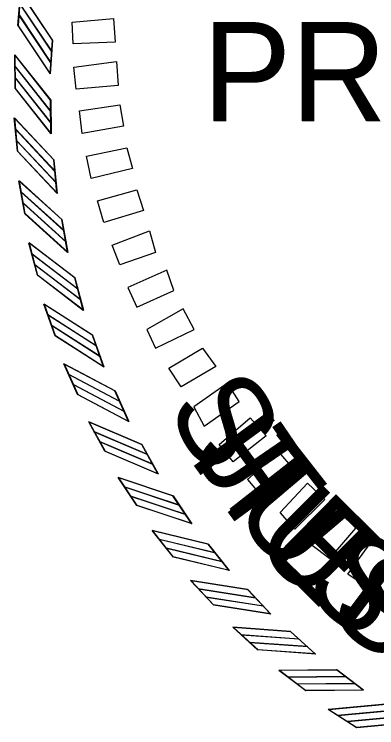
# Model space of a CAD drawing. Extents: x 16 to 1228740, y 11 to 152440.
# Drawn here: x 17.6792 to 17.7202, y 10.8292 to 10.9098 of the extents above; entities that cross this region are included whole.
import ezdxf

# ---------------------------------------------------------------- set-up
doc = ezdxf.new("R2010")
doc.units = 0
for name, color, linetype in [('STAMP_FRED', 7, 'Continuous'), ('STAMP_HUSSAM', 7, 'Continuous'), ('STAMP_JUSTIN', 7, 'Continuous'), ('STAMP_PRELIM', 7, 'Continuous')]:
    doc.layers.add(name, color=color, linetype=linetype)

msp = doc.modelspace()

# ---------------------------------------------------------------- linework, layer by layer
at = {"layer": 'STAMP_FRED'}
for p, q in [((17.6797, 10.908524), (17.679977, 10.912284)), ((17.683323, 10.903099), (17.683601, 10.906868)), ((17.67937, 10.901425), (17.679335, 10.905195)), ((17.683429, 10.896318), (17.683394, 10.900096)), ((17.679627, 10.894324), (17.679282, 10.898078)), ((17.684094, 10.889569), (17.683748, 10.893331)), ((17.680471, 10.887267), (17.679816, 10.89098)), ((17.685315, 10.882897), (17.684658, 10.886619)), ((17.681893, 10.880305), (17.680934, 10.883951)), ((17.687082, 10.87635), (17.686121, 10.880004)), ((17.683886, 10.873483), (17.682629, 10.877038)), ((17.689384, 10.86997), (17.688124, 10.873533)), ((17.686436, 10.86685), (17.68489, 10.870288)), ((17.692204, 10.863803), (17.690655, 10.867249)), ((17.689524, 10.86045), (17.6877, 10.863749)), ((17.695525, 10.857889), (17.693696, 10.861196)), ((17.693131, 10.854326), (17.69104, 10.857463)), ((17.699322, 10.85227), (17.697227, 10.855415)), ((17.697231, 10.848522), (17.694888, 10.851475)), ((17.703571, 10.846984), (17.701223, 10.849945)), ((17.701796, 10.843075), (17.699217, 10.845825)), ((17.708241, 10.842067), (17.705657, 10.844823)), ((17.706795, 10.838025), (17.703998, 10.840552)), ((17.713302, 10.837552), (17.710498, 10.840085)), ((17.712195, 10.833404), (17.709198, 10.835692)), ((17.718718, 10.83347), (17.715715, 10.835764)), ((17.717957, 10.829245), (17.714782, 10.831278))]:
    msp.add_line(p, q, dxfattribs=at)
for points in [[(17.683598, 10.906863), (17.679974, 10.912288)], [(17.683494, 10.905612), (17.679871, 10.911036)], [(17.683427, 10.904304), (17.679803, 10.909728)], [(17.683326, 10.903094), (17.679703, 10.908519)], [(17.683392, 10.900092), (17.679333, 10.905199)], [(17.683392, 10.898836), (17.679333, 10.903943)], [(17.683433, 10.897527), (17.679374, 10.902633)], [(17.683433, 10.896313), (17.679374, 10.90142)], [(17.683745, 10.893327), (17.679279, 10.898081)], [(17.683849, 10.892075), (17.679382, 10.896829)], [(17.683998, 10.890774), (17.679531, 10.895528)], [(17.684098, 10.889565), (17.679632, 10.894319)], [(17.684657, 10.886614), (17.679813, 10.890983)], [(17.684863, 10.885375), (17.680019, 10.889744)], [(17.685119, 10.884091), (17.680275, 10.888459)], [(17.685319, 10.882894), (17.680475, 10.887263)], [(17.686119, 10.879999), (17.680931, 10.883953)], [(17.686427, 10.878782), (17.681239, 10.882736)], [(17.686789, 10.877523), (17.6816, 10.881477)], [(17.687086, 10.876346), (17.681898, 10.8803)], [(17.688123, 10.873528), (17.682626, 10.87704)], [(17.688531, 10.87234), (17.683034, 10.875852)], [(17.688995, 10.871115), (17.683497, 10.874627)], [(17.689389, 10.869967), (17.683891, 10.873479)], [(17.690654, 10.867244), (17.684886, 10.87029)], [(17.691159, 10.866094), (17.68539, 10.86914)], [(17.691722, 10.864912), (17.685954, 10.867958)], [(17.69221, 10.8638), (17.686441, 10.866846)], [(17.693696, 10.861191), (17.687696, 10.86375)], [(17.694293, 10.860086), (17.688293, 10.862646)], [(17.694953, 10.858954), (17.688953, 10.861514)], [(17.69553, 10.857887), (17.68953, 10.860447)], [(17.697227, 10.855409), (17.691036, 10.857465)], [(17.697914, 10.854358), (17.691723, 10.856413)], [(17.698664, 10.853284), (17.692473, 10.85534)], [(17.699328, 10.852269), (17.693137, 10.854324)], [(17.701223, 10.849939), (17.694884, 10.851476)], [(17.701995, 10.848948), (17.695655, 10.850485)], [(17.702831, 10.84794), (17.696492, 10.849477)], [(17.703576, 10.846983), (17.697237, 10.84852)], [(17.705658, 10.844818), (17.699213, 10.845826)], [(17.706508, 10.843894), (17.700063, 10.844902)], [(17.707425, 10.842959), (17.70098, 10.843967)], [(17.708247, 10.842066), (17.701802, 10.843074)], [(17.7105, 10.84008), (17.703994, 10.840553)], [(17.711424, 10.83923), (17.704918, 10.839702)], [(17.712415, 10.838373), (17.705909, 10.838846)], [(17.713308, 10.837551), (17.706802, 10.838024)], [(17.715717, 10.835759), (17.709194, 10.835692)], [(17.716708, 10.834987), (17.710185, 10.834921)], [(17.717766, 10.834216), (17.711243, 10.834149)], [(17.718724, 10.83347), (17.712201, 10.833404)], [(17.721273, 10.831883), (17.714778, 10.831278)], [(17.722324, 10.831196), (17.715829, 10.830591)], [(17.723443, 10.830514), (17.716948, 10.829909)], [(17.724459, 10.82985), (17.717964, 10.829245)]]:
    msp.add_lwpolyline(points, dxfattribs=at)
at = {"layer": 'STAMP_HUSSAM'}
for p, q in [((17.679644, 10.908555), (17.679921, 10.912315)), ((17.683267, 10.90313), (17.683545, 10.906898)), ((17.679314, 10.901456), (17.67928, 10.905226)), ((17.683373, 10.896349), (17.683338, 10.900127)), ((17.679572, 10.894354), (17.679226, 10.898108)), ((17.684039, 10.8896), (17.683692, 10.893362)), ((17.680415, 10.887298), (17.67976, 10.891011)), ((17.685259, 10.882928), (17.684603, 10.88665)), ((17.681838, 10.880335), (17.680879, 10.883981)), ((17.687026, 10.876381), (17.686065, 10.880035)), ((17.683831, 10.873514), (17.682574, 10.877068)), ((17.689328, 10.870001), (17.688068, 10.873564)), ((17.68638, 10.866881), (17.684834, 10.870319)), ((17.692149, 10.863834), (17.690599, 10.86728)), ((17.689469, 10.86048), (17.687644, 10.863779)), ((17.695469, 10.85792), (17.69364, 10.861227)), ((17.693075, 10.854357), (17.690984, 10.857494)), ((17.699267, 10.852301), (17.697171, 10.855446)), ((17.697175, 10.848552), (17.694832, 10.851506)), ((17.703515, 10.847015), (17.701167, 10.849975)), ((17.70174, 10.843106), (17.699161, 10.845856)), ((17.708186, 10.842098), (17.705601, 10.844854)), ((17.706739, 10.838056), (17.703942, 10.840583)), ((17.713246, 10.837583), (17.710443, 10.840116)), ((17.712139, 10.833435), (17.709143, 10.835723)), ((17.718662, 10.833501), (17.715659, 10.835794)), ((17.717901, 10.829276), (17.714726, 10.831309))]:
    msp.add_line(p, q, dxfattribs=at)
for points in [[(17.683542, 10.906894), (17.679918, 10.912319)], [(17.683438, 10.905643), (17.679815, 10.911067)], [(17.683371, 10.904334), (17.679748, 10.909759)], [(17.683271, 10.903125), (17.679647, 10.908549)], [(17.683336, 10.900123), (17.679277, 10.905229)], [(17.683336, 10.898867), (17.679277, 10.903974)], [(17.683377, 10.897558), (17.679318, 10.902664)], [(17.683377, 10.896344), (17.679318, 10.901451)], [(17.68369, 10.893358), (17.679223, 10.898112)], [(17.683793, 10.892106), (17.679327, 10.89686)], [(17.683942, 10.890805), (17.679476, 10.895559)], [(17.684042, 10.889595), (17.679576, 10.894349)], [(17.684601, 10.886645), (17.679757, 10.891014)], [(17.684808, 10.885406), (17.679964, 10.889775)], [(17.685063, 10.884121), (17.680219, 10.88849)], [(17.685263, 10.882924), (17.680419, 10.887293)], [(17.686063, 10.88003), (17.680875, 10.883984)], [(17.686372, 10.878813), (17.681183, 10.882767)], [(17.686733, 10.877553), (17.681545, 10.881507)], [(17.687031, 10.876377), (17.681842, 10.880331)], [(17.688067, 10.873559), (17.68257, 10.877071)], [(17.688475, 10.872371), (17.682978, 10.875883)], [(17.688939, 10.871146), (17.683442, 10.874658)], [(17.689333, 10.869998), (17.683836, 10.87351)], [(17.690598, 10.867275), (17.68483, 10.870321)], [(17.691103, 10.866125), (17.685335, 10.869171)], [(17.691666, 10.864942), (17.685898, 10.867988)], [(17.692154, 10.863831), (17.686385, 10.866877)], [(17.69364, 10.861222), (17.68764, 10.863781)], [(17.694238, 10.860117), (17.688238, 10.862677)], [(17.694897, 10.858985), (17.688897, 10.861545)], [(17.695474, 10.857918), (17.689474, 10.860477)], [(17.697171, 10.85544), (17.69098, 10.857495)], [(17.697858, 10.854389), (17.691667, 10.856444)], [(17.698608, 10.853315), (17.692417, 10.85537)], [(17.699272, 10.852299), (17.693081, 10.854355)], [(17.701167, 10.84997), (17.694828, 10.851507)], [(17.701939, 10.848979), (17.695599, 10.850516)], [(17.702775, 10.847971), (17.696436, 10.849508)], [(17.703521, 10.847014), (17.697181, 10.84855)], [(17.705602, 10.844849), (17.699157, 10.845857)], [(17.706453, 10.843925), (17.700008, 10.844933)], [(17.707369, 10.842989), (17.700925, 10.843997)], [(17.708191, 10.842097), (17.701746, 10.843105)], [(17.710444, 10.840111), (17.703938, 10.840584)], [(17.711368, 10.839261), (17.704862, 10.839733)], [(17.712359, 10.838404), (17.705853, 10.838876)], [(17.713252, 10.837582), (17.706746, 10.838055)], [(17.715661, 10.83579), (17.709138, 10.835723)], [(17.716652, 10.835018), (17.710129, 10.834952)], [(17.717711, 10.834246), (17.711188, 10.83418)], [(17.718668, 10.833501), (17.712145, 10.833435)], [(17.721217, 10.831914), (17.714722, 10.831309)], [(17.722269, 10.831227), (17.715773, 10.830622)], [(17.723387, 10.830545), (17.716892, 10.82994)], [(17.724403, 10.829881), (17.717908, 10.829276)]]:
    msp.add_lwpolyline(points, dxfattribs=at)
at = {"layer": 'STAMP_JUSTIN'}
for p, q in [((17.679702, 10.908525), (17.679979, 10.912285)), ((17.683325, 10.9031), (17.683602, 10.906868)), ((17.679372, 10.901426), (17.679337, 10.905196)), ((17.683431, 10.896319), (17.683396, 10.900097)), ((17.679629, 10.894325), (17.679283, 10.898079)), ((17.684096, 10.88957), (17.683749, 10.893333)), ((17.680472, 10.887269), (17.679818, 10.890981)), ((17.685316, 10.882899), (17.68466, 10.88662)), ((17.681895, 10.880306), (17.680936, 10.883952)), ((17.687084, 10.876351), (17.686122, 10.880006)), ((17.683888, 10.873485), (17.682631, 10.877039)), ((17.689385, 10.869972), (17.688126, 10.873535)), ((17.686437, 10.866852), (17.684891, 10.87029)), ((17.692206, 10.863805), (17.690656, 10.867251)), ((17.689526, 10.860452), (17.687701, 10.86375)), ((17.695526, 10.857891), (17.693697, 10.861198)), ((17.693132, 10.854328), (17.691042, 10.857465)), ((17.699324, 10.852273), (17.697228, 10.855417)), ((17.697232, 10.848524), (17.694889, 10.851477)), ((17.703572, 10.846986), (17.701224, 10.849947)), ((17.701797, 10.843078), (17.699219, 10.845828)), ((17.708243, 10.842069), (17.705658, 10.844825)), ((17.706796, 10.838027), (17.704, 10.840555)), ((17.713303, 10.837554), (17.7105, 10.840088)), ((17.712196, 10.833407), (17.7092, 10.835695)), ((17.718719, 10.833473), (17.715716, 10.835766)), ((17.717958, 10.829248), (17.714783, 10.831281))]:
    msp.add_line(p, q, dxfattribs=at)
for points in [[(17.683599, 10.906864), (17.679976, 10.912288)], [(17.683496, 10.905613), (17.679872, 10.911037)], [(17.683428, 10.904304), (17.679805, 10.909729)], [(17.683328, 10.903095), (17.679705, 10.908519)], [(17.683393, 10.900093), (17.679335, 10.9052)], [(17.683393, 10.898837), (17.679335, 10.903944)], [(17.683434, 10.897528), (17.679376, 10.902634)], [(17.683434, 10.896314), (17.679376, 10.901421)], [(17.683747, 10.893328), (17.67928, 10.898082)], [(17.683851, 10.892076), (17.679384, 10.89683)], [(17.684, 10.890775), (17.679533, 10.895529)], [(17.6841, 10.889566), (17.679633, 10.89432)], [(17.684658, 10.886615), (17.679814, 10.890984)], [(17.684865, 10.885376), (17.680021, 10.889745)], [(17.685121, 10.884092), (17.680277, 10.888461)], [(17.685321, 10.882895), (17.680477, 10.887264)], [(17.686121, 10.880001), (17.680933, 10.883955)], [(17.686429, 10.878783), (17.681241, 10.882737)], [(17.68679, 10.877524), (17.681602, 10.881478)], [(17.687088, 10.876348), (17.6819, 10.880302)], [(17.688125, 10.87353), (17.682628, 10.877041)], [(17.688532, 10.872342), (17.683035, 10.875854)], [(17.688996, 10.871117), (17.683499, 10.874629)], [(17.68939, 10.869969), (17.683893, 10.873481)], [(17.690656, 10.867246), (17.684888, 10.870292)], [(17.69116, 10.866096), (17.685392, 10.869142)], [(17.691724, 10.864913), (17.685956, 10.867959)], [(17.692211, 10.863802), (17.686443, 10.866848)], [(17.693697, 10.861193), (17.687697, 10.863752)], [(17.694295, 10.860088), (17.688295, 10.862648)], [(17.694954, 10.858956), (17.688954, 10.861516)], [(17.695532, 10.857889), (17.689532, 10.860449)], [(17.697228, 10.855412), (17.691037, 10.857467)], [(17.697915, 10.85436), (17.691724, 10.856415)], [(17.698666, 10.853287), (17.692475, 10.855342)], [(17.699329, 10.852271), (17.693138, 10.854326)], [(17.701225, 10.849942), (17.694885, 10.851478)], [(17.701996, 10.848951), (17.695656, 10.850487)], [(17.702832, 10.847943), (17.696493, 10.849479)], [(17.703578, 10.846985), (17.697238, 10.848522)], [(17.705659, 10.84482), (17.699214, 10.845828)], [(17.70651, 10.843896), (17.700065, 10.844904)], [(17.707426, 10.842961), (17.700982, 10.843969)], [(17.708248, 10.842068), (17.701804, 10.843076)], [(17.710501, 10.840083), (17.703995, 10.840555)], [(17.711425, 10.839232), (17.704919, 10.839705)], [(17.712416, 10.838376), (17.70591, 10.838848)], [(17.713309, 10.837554), (17.706803, 10.838026)], [(17.715718, 10.835761), (17.709195, 10.835695)], [(17.716709, 10.83499), (17.710186, 10.834923)], [(17.717767, 10.834218), (17.711245, 10.834152)], [(17.718725, 10.833473), (17.712202, 10.833406)], [(17.721274, 10.831885), (17.714779, 10.83128)], [(17.722325, 10.831198), (17.71583, 10.830593)], [(17.723444, 10.830517), (17.716949, 10.829912)], [(17.724459, 10.829853), (17.717964, 10.829248)]]:
    msp.add_lwpolyline(points, dxfattribs=at)
at = {"layer": 'STAMP_PRELIM'}
for p, q in [((17.685777, 10.908908), (17.69046, 10.90935)), ((17.69046, 10.90935), (17.690652, 10.906658)), ((17.685902, 10.906475), (17.685777, 10.908908)), ((17.690652, 10.906658), (17.685902, 10.906475)), ((17.68596, 10.90385), (17.690777, 10.904475)), ((17.690777, 10.904475), (17.69096, 10.901783)), ((17.68621, 10.90135), (17.68596, 10.90385)), ((17.69096, 10.901783), (17.68621, 10.90135)), ((17.686585, 10.898908), (17.691152, 10.8996)), ((17.691152, 10.8996), (17.691585, 10.897158)), ((17.686902, 10.89635), (17.686585, 10.898908)), ((17.691585, 10.897158), (17.686902, 10.89635)), ((17.687402, 10.893783), (17.69196, 10.894725)), ((17.69196, 10.894725), (17.692585, 10.892408)), ((17.687902, 10.891283), (17.687402, 10.893783)), ((17.692585, 10.892408), (17.687902, 10.891283)), ((17.688652, 10.888725), (17.693085, 10.889975)), ((17.693085, 10.889975), (17.693835, 10.887658)), ((17.689335, 10.886283), (17.688652, 10.888725)), ((17.693835, 10.887658), (17.689335, 10.886283)), ((17.690277, 10.883725), (17.694527, 10.88535)), ((17.694527, 10.88535), (17.69521, 10.882908)), ((17.691152, 10.881533), (17.690277, 10.883725)), ((17.69521, 10.882908), (17.691152, 10.881533)), ((17.69646, 10.880908), (17.692085, 10.878975)), ((17.697277, 10.8786), (17.69646, 10.880908)), ((17.692085, 10.878975), (17.693085, 10.876725)), ((17.693085, 10.876725), (17.697277, 10.8786)), ((17.698335, 10.876533), (17.69421, 10.874225)), ((17.699585, 10.874225), (17.698335, 10.876533)), ((17.69421, 10.874225), (17.69521, 10.8721)), ((17.69521, 10.8721), (17.699585, 10.874225)), ((17.69671, 10.86985), (17.700527, 10.8721)), ((17.700527, 10.8721), (17.702027, 10.870033)), ((17.698085, 10.867725), (17.69671, 10.86985)), ((17.702027, 10.870033), (17.698085, 10.867725)), ((17.703335, 10.868158), (17.699527, 10.865475)), ((17.704652, 10.8661), (17.703335, 10.868158)), ((17.70071, 10.863283), (17.704652, 10.8661)), ((17.699527, 10.865475), (17.70071, 10.863283)), ((17.702402, 10.861225), (17.705902, 10.864225)), ((17.705902, 10.864225), (17.70771, 10.862225)), ((17.70771, 10.862225), (17.70396, 10.859283)), ((17.70396, 10.859283), (17.702402, 10.861225)), ((17.709152, 10.860408), (17.705585, 10.857283)), ((17.710777, 10.858533), (17.709152, 10.860408)), ((17.70721, 10.85535), (17.710777, 10.858533)), ((17.705585, 10.857283), (17.70721, 10.85535)), ((17.709277, 10.853533), (17.712402, 10.85685)), ((17.712402, 10.85685), (17.714335, 10.855033)), ((17.714335, 10.855033), (17.71096, 10.851658)), ((17.71096, 10.851658), (17.709277, 10.853533)), ((17.716027, 10.853533), (17.712777, 10.849975)), ((17.717835, 10.851783), (17.716027, 10.853533)), ((17.714902, 10.84835), (17.717835, 10.851783)), ((17.71696, 10.8466), (17.719777, 10.850475)), ((17.719777, 10.850475), (17.72171, 10.848908)), ((17.712777, 10.849975), (17.714902, 10.84835)), ((17.72171, 10.848908), (17.718902, 10.845283)), ((17.718902, 10.845283), (17.71696, 10.8466))]:
    msp.add_line(p, q, dxfattribs=at)

# ---------------------------------------------------------------- texts
at = {"layer": 'STAMP_FRED'}
msp.add_text('PROFESSIONAL', height=0.01119382, dxfattribs=at).set_placement((17.700561, 10.897711))
for s, rotation, p in [('S', 300.79847, (17.696258, 10.865347)), ('T', 308.09448, (17.701345, 10.856814)), ('E', 315.39049, (17.707475, 10.848997)), ('P', 323.0513, (17.714924, 10.841696))]:
    msp.add_text(s, height=0.010417, rotation=rotation, dxfattribs=at).set_placement(p)
at = {"layer": 'STAMP_HUSSAM'}
msp.add_text('PROFESSIONAL', height=0.01119382, dxfattribs=at).set_placement((17.700506, 10.897742))
for s, rotation, p in [('H', 306.22623, (17.69885, 10.859742)), ('U', 314.9716, (17.7059, 10.850121)), ('S', 323.71697, (17.714331, 10.841684))]:
    msp.add_text(s, height=0.010417, rotation=rotation, dxfattribs=at).set_placement(p)
at = {"layer": 'STAMP_JUSTIN'}
msp.add_text('PROFESSIONAL', height=0.01119355, dxfattribs=at).set_placement((17.700563, 10.897712))
for s, rotation, p in [('J', 304.36793, (17.699173, 10.860274)), ('U', 310.20474, (17.703657, 10.853718)), ('S', 318.95995, (17.711573, 10.844822))]:
    msp.add_text(s, height=0.010416, rotation=rotation, dxfattribs=at).set_placement(p)

doc.saveas('drawing.dxf')
